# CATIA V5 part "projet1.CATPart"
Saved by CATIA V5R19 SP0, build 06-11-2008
Part number: Part3
Bounding box of the stored display mesh (mm): x 0 to 300, y -175.23 to 226.679, z -74.002 to 221.503
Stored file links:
  C:\Documents and Settings\Administrateur\Bureau\projet I\projet1.CATPart
  C:\Documents and Settings\Administrateur\Bureau\cat\conne1.CATPart
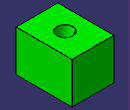
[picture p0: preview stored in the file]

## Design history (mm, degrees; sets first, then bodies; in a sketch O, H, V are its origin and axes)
Chamfer1: length 1, angle 45, on face of Pad1 from Sketch1.L1; start face of Pad1; face of Pad1 from Sketch1.L3; edge [face of Pad1 from Sketch1.L1 | face of Pad1 from Sketch1.L2]; end face of Pad1
Body1 (main body)
  Sketch1 on yz-plane, origin (0, 0, 0), H (0, 1, 0), V (0, 0, 1)
    line L1 (-175.2302, 221.5029) -> (226.6789, 221.5029)
    line L2 (226.6789, 221.5029) -> (226.6789, -74.0021)
    line L3 (226.6789, -74.0021) -> (-175.2302, -74.0021)
    line L4 (-175.2302, -74.0021) -> (-175.2302, 221.5029)
    horizontal: L1 H, L3 H
    vertical: L2 V, L4 V
  Pad1: profile Sketch1, direction (1, 0, 0), length 300
  Sketch2 on end face of Pad1, origin (300, 0, 0), H (0, 1, 0), V (0, 0, 1)
  Sketch3 on face of Pad1 from Sketch1.L1, origin (113.2057, 5.0735, 221.5029), H (1, 0, 0), V (0, 1, 0)
    point P1 (36.7943, 20.6508)
    reference projected line E1 (-113.2057, -180.3037) -> (186.7943, -180.3037) from edge [face of Pad1 from Sketch1.L4 | face of Pad1 from Sketch1.L1]
    reference projected line E2 (-113.2057, 221.6054) -> (-113.2057, -180.3037) from edge [start face of Pad1 | face of Pad1 from Sketch1.L1]
    distance P1 E1 = 200.9545
    distance P1 E2 = 150
  Hole1: placed by Sketch3, at (150, 25.7243, 221.5029) direction (0, 0, -1), diameter 40, depth 100, type TaperedType, Pas 1, DiameterThread 11, Profile a sketch, ThreadDepth 10, Diameter 40, Sketch Sketch3, Angle 40
Current feature: Chamfer1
